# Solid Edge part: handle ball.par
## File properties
Title: Handle Ball
Author: Abhinva Rai
Template: Normal.par
Last saved by: CADCIM
Revision: 10
Application: Solid Edge
Density: 0.0000078 kg/mm^3
Accuracy: 0.01
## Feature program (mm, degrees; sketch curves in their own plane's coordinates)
sketch for "unnamed RevolvedProtrusion 1" plane through (0, 0, 0) normal (0, -1, 0) x-axis (1, 0, 0)
  arc centre (0, 0) radius 9.525 from (0, 9.525) to (0, -9.525) cw
  line (0, 9.525) -> (0, -9.525)
revolve "unnamed RevolvedProtrusion 1" add finite 360 deg
sketch for "unnamed Cutout 1" plane through (0, 0, 0) normal (0, -1, 0) x-axis (1, 0, 0)
  circle centre (0, 0) radius 3.9751
extrude "unnamed Cutout 1" cut finite 50.8 symmetric
sketch for "ExtrudedCutout_2" plane through (0, 0, 0) normal (0, 0, 1) x-axis (1, 0, 0)
  circle centre (0, 0) radius 1.905
extrude "ExtrudedCutout_2" cut finite 50.8 symmetric
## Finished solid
Body 1: solid body, 4 faces, 6 edges, 0 vertices.
  Faces by surface: cylinder 3, sphere 1
  Edges by curve: circle 4, intersection 2
Bounding box of the edges (mm; curved faces can reach further): 7.950 x 17.312 x 18.665, from (-3.9751, -8.6559, -9.3326) to (3.9751, 8.6559, 9.3326).
Cylindrical faces by radius (mm): R1.905 x2, R3.9751 x1
Spherical faces by radius (mm): R9.525 x1
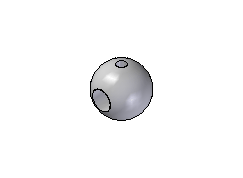
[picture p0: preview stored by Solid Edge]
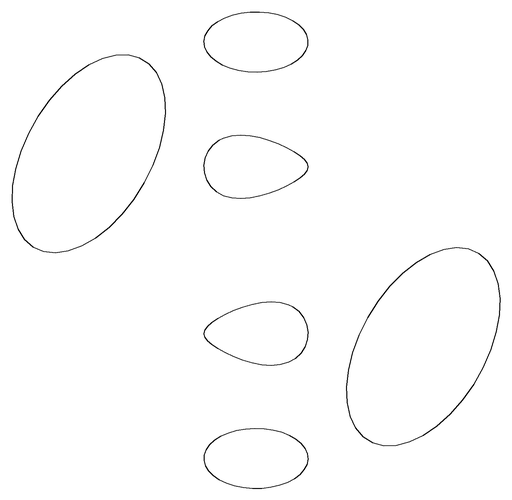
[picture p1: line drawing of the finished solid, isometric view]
